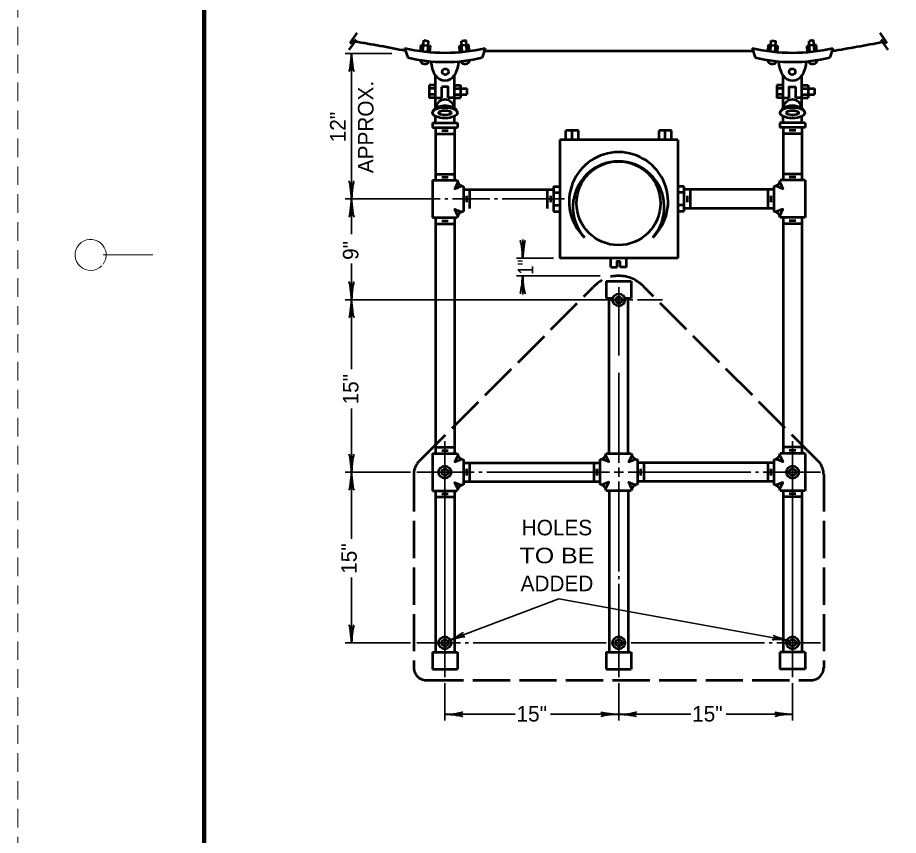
# Model space of a CAD drawing. Extents: x -1 to 679, y 1 to 441.
# Drawn here: x -1.2 to 140.6, y 193.5 to 325.3 of the extents above; entities that cross this region are included whole.
import ezdxf
from ezdxf.enums import TextEntityAlignment as Align

# ---------------------------------------------------------------- set-up
doc = ezdxf.new("R2010")
doc.units = 0
doc.linetypes.add('LONG_DASHED', pattern=[7.5, 6, -1.5])
doc.linetypes.add('MEDIUM_DASHED', pattern=[4.5, 3, -1.5])
doc.layers.add('1', color=7, linetype='Continuous', lineweight=35)
doc.layers.add('61', color=7, linetype='Continuous', lineweight=35)

msp = doc.modelspace()

# ---------------------------------------------------------------- linework, layer by layer
at = {"layer": '1', "linetype": 'MEDIUM_DASHED', "lineweight": 13}
msp.add_line((-1.178, 440.796), (-1.238, 0.756), dxfattribs=at)
at = {"layer": '1', "lineweight": 53}
for p, q in [((52.31, 321.145), (53.457, 322.783)), ((138.783, 321.145), (137.636, 322.783)), ((52.158, 320.046), (53.305, 321.684)), ((52.31, 321.145), (53.305, 321.684)), ((63.653, 319.875), (63.743, 320.896)), ((63.743, 320.896), (65.229, 320.695)), ((64.029, 319.867), (64.181, 321.61)), ((64.181, 321.61), (64.907, 321.469)), ((64.785, 319.723), (64.907, 321.469)), ((65.16, 319.707), (65.229, 320.695)), ((71.413, 320.86), (69.912, 320.692)), ((69.981, 319.708), (69.912, 320.692)), ((70.987, 321.582), (70.234, 321.467)), ((70.356, 319.721), (70.234, 321.467)), ((71.109, 319.836), (70.987, 321.582)), ((71.482, 319.875), (71.413, 320.86)), ((119.611, 319.875), (119.68, 320.86)), ((119.68, 320.86), (121.181, 320.692)), ((119.985, 319.836), (120.107, 321.582)), ((120.107, 321.582), (120.859, 321.467)), ((120.737, 319.721), (120.859, 321.467)), ((121.112, 319.708), (121.181, 320.692)), ((127.351, 320.896), (125.864, 320.695)), ((125.933, 319.707), (125.864, 320.695)), ((126.912, 321.61), (126.186, 321.469)), ((126.308, 319.723), (126.186, 321.469)), ((127.064, 319.867), (126.912, 321.61)), ((127.44, 319.875), (127.351, 320.896)), ((138.936, 320.046), (137.788, 321.684)), ((138.783, 321.145), (137.788, 321.684)), ((61.069, 320.356), (61.569, 318.856)), ((74.069, 320.356), (73.569, 318.856)), ((73.911, 319.881), (117.182, 319.881)), ((117.024, 320.356), (117.524, 318.856)), ((130.024, 320.356), (129.524, 318.856)), ((66.047, 310.652), (66.047, 315.963)), ((69.092, 310.652), (69.092, 315.963)), ((122.001, 310.652), (122.001, 315.963)), ((125.047, 310.652), (125.047, 315.963)), ((66.047, 314.356), (65.047, 314.356)), ((65.047, 314.356), (65.047, 312.356)), ((66.047, 313.856), (65.047, 313.856)), ((67.047, 312.356), (67.047, 314.106)), ((69.092, 314.356), (70.092, 314.356)), ((69.092, 313.856), (71.092, 313.856)), ((70.092, 314.356), (70.092, 312.356)), ((71.092, 313.856), (71.092, 312.856)), ((122.001, 314.356), (121.001, 314.356)), ((121.001, 314.356), (121.001, 312.356)), ((122.001, 313.856), (121.001, 313.856)), ((124.047, 312.356), (124.047, 314.106)), ((125.047, 314.356), (126.047, 314.356)), ((125.047, 313.856), (127.047, 313.856)), ((126.047, 314.356), (126.047, 312.356)), ((127.047, 313.856), (127.047, 312.856)), ((66.047, 312.856), (65.047, 312.856)), ((66.047, 312.356), (65.047, 312.356)), ((66.047, 312.356), (67.047, 312.356)), ((69.092, 312.356), (68.092, 312.356)), ((69.092, 312.856), (71.092, 312.856)), ((69.092, 312.356), (70.092, 312.356)), ((122.001, 312.856), (121.001, 312.856)), ((122.001, 312.356), (121.001, 312.356)), ((122.001, 312.356), (123.001, 312.356)), ((125.047, 312.356), (124.047, 312.356)), ((125.047, 312.856), (127.047, 312.856)), ((125.047, 312.356), (126.047, 312.356)), ((66.047, 308.298), (66.047, 309.356)), ((69.092, 308.298), (69.092, 309.356)), ((122.001, 308.298), (122.001, 309.356)), ((125.047, 308.298), (125.047, 309.356)), ((65.547, 308.298), (69.592, 308.298)), ((65.547, 308.298), (65.547, 307.548)), ((69.592, 308.298), (69.592, 307.548)), ((125.547, 308.298), (121.501, 308.298)), ((121.501, 308.298), (121.501, 307.548)), ((125.547, 308.298), (125.547, 307.548)), ((65.547, 307.548), (69.592, 307.548)), ((66.047, 307.548), (66.047, 299.048)), ((66.047, 306.548), (69.092, 306.548)), ((67.047, 307.048), (68.092, 307.048)), ((69.092, 307.548), (69.092, 299.048)), ((87.047, 305.57), (87.047, 307.07)), ((89.047, 307.07), (87.047, 307.07)), ((88.047, 305.57), (88.047, 307.07)), ((89.047, 305.57), (89.047, 307.07)), ((102.047, 305.57), (102.047, 307.07)), ((104.047, 307.07), (102.047, 307.07)), ((103.047, 305.57), (103.047, 307.07)), ((104.047, 305.57), (104.047, 307.07)), ((125.547, 307.548), (121.501, 307.548)), ((122.001, 307.548), (122.001, 299.048)), ((125.047, 306.548), (122.001, 306.548)), ((124.047, 307.048), (123.001, 307.048)), ((125.047, 307.548), (125.047, 299.048)), ((105.047, 305.57), (86.047, 305.57)), ((86.047, 305.57), (86.047, 286.536)), ((105.047, 305.57), (105.047, 286.536)), ((66.047, 300.048), (69.092, 300.048)), ((67.047, 299.548), (68.092, 299.548)), ((125.047, 300.048), (122.001, 300.048)), ((124.047, 299.548), (123.001, 299.548)), ((65.547, 299.048), (69.546, 299.048)), ((65.547, 299.048), (65.547, 293.048)), ((70.547, 298.07), (70.547, 294.025)), ((85.047, 298.07), (85.047, 294.036)), ((85.047, 298.07), (86.047, 298.07)), ((106.047, 298.07), (105.047, 298.07)), ((106.047, 298.07), (106.047, 294.036)), ((120.547, 298.07), (120.547, 294.025)), ((125.547, 299.048), (121.548, 299.048)), ((125.547, 299.048), (125.547, 293.048)), ((70.547, 297.57), (85.047, 297.57)), ((71.047, 296.57), (71.047, 295.525)), ((71.547, 297.57), (71.547, 294.525)), ((84.047, 297.57), (84.047, 294.525)), ((84.547, 296.57), (84.547, 295.525)), ((85.047, 297.07), (86.047, 297.07)), ((106.047, 297.07), (105.047, 297.07)), ((120.547, 297.57), (106.047, 297.57)), ((106.547, 296.57), (106.547, 295.525)), ((107.047, 297.57), (107.047, 294.525)), ((119.547, 297.57), (119.547, 294.525)), ((120.047, 296.57), (120.047, 295.525)), ((85.047, 295.036), (86.047, 295.036)), ((106.047, 295.036), (105.047, 295.036)), ((85.047, 294.036), (86.047, 294.036)), ((106.047, 294.036), (105.047, 294.036)), ((120.547, 294.525), (106.047, 294.525)), ((65.547, 293.048), (69.542, 293.048)), ((66.047, 293.048), (66.047, 255.048)), ((66.047, 293.048), (69.092, 293.048)), ((67.047, 292.548), (68.092, 292.548)), ((69.092, 293.048), (69.092, 255.048)), ((125.547, 293.048), (121.551, 293.048)), ((122.001, 293.048), (122.001, 255.048)), ((125.047, 293.048), (122.001, 293.048)), ((124.047, 292.548), (123.001, 292.548)), ((125.047, 293.048), (125.047, 255.048)), ((66.047, 292.048), (69.092, 292.048)), ((125.047, 292.048), (122.001, 292.048)), ((105.047, 286.536), (86.047, 286.536)), ((94.297, 285.036), (94.297, 286.536)), ((96.797, 285.036), (96.797, 286.536)), ((95.797, 285.036), (95.797, 286.036)), ((94.297, 285.036), (95.297, 285.036)), ((96.797, 285.036), (95.797, 285.036)), ((93.524, 282.814), (97.569, 282.814)), ((93.524, 282.814), (93.524, 280.064)), ((97.569, 282.814), (97.569, 280.064)), ((93.524, 280.064), (94.595, 280.064)), ((94.024, 255.064), (94.024, 280.064)), ((96.518, 280.064), (97.569, 280.064)), ((97.069, 255.064), (97.069, 280.064)), ((66.047, 256.048), (69.092, 256.048)), ((67.047, 255.548), (68.092, 255.548)), ((125.047, 256.048), (122.001, 256.048)), ((124.047, 255.548), (123.001, 255.548)), ((65.547, 255.048), (69.546, 255.048)), ((65.547, 255.048), (65.547, 249.048)), ((70.547, 254.07), (70.547, 250.025)), ((92.524, 254.07), (92.524, 250.064)), ((93.524, 255.064), (97.569, 255.064)), ((98.572, 254.07), (98.572, 250.058)), ((120.547, 254.07), (120.547, 250.025)), ((125.547, 255.048), (121.548, 255.048)), ((125.547, 255.048), (125.547, 249.048)), ((70.547, 253.57), (92.524, 253.57)), ((71.047, 252.57), (71.047, 251.525)), ((71.547, 253.57), (71.547, 250.525)), ((91.524, 253.57), (91.524, 250.525)), ((92.024, 252.57), (92.024, 251.525)), ((120.547, 253.57), (98.572, 253.57)), ((99.072, 252.57), (99.072, 251.525)), ((99.572, 253.57), (99.572, 250.525)), ((119.547, 253.57), (119.547, 250.525)), ((120.047, 252.57), (120.047, 251.525)), ((70.547, 250.525), (92.524, 250.525)), ((120.547, 250.525), (98.572, 250.525)), ((65.547, 249.048), (69.542, 249.048)), ((66.047, 249.048), (66.047, 223.048)), ((67.047, 248.548), (68.092, 248.548)), ((69.092, 249.048), (69.092, 223.048)), ((93.531, 249.064), (97.565, 249.064)), ((94.031, 249.064), (94.031, 223.064)), ((97.065, 249.064), (97.065, 223.064)), ((125.547, 249.048), (121.551, 249.048)), ((122.001, 249.048), (122.001, 223.048)), ((124.047, 248.548), (123.001, 248.548)), ((125.047, 249.048), (125.047, 223.048)), ((66.047, 248.048), (69.092, 248.048)), ((125.047, 248.048), (122.001, 248.048)), ((65.547, 223.048), (69.592, 223.048)), ((65.547, 223.048), (65.547, 220.298)), ((69.592, 223.048), (69.592, 220.298)), ((93.531, 223.064), (97.576, 223.064)), ((93.531, 223.064), (93.531, 220.314)), ((97.576, 223.064), (97.576, 220.314)), ((125.547, 223.048), (121.501, 223.048)), ((121.501, 223.048), (121.501, 220.298)), ((125.547, 223.048), (125.547, 220.298)), ((65.547, 220.298), (69.592, 220.298)), ((93.531, 220.314), (97.576, 220.314)), ((125.547, 220.298), (121.501, 220.298))]:
    msp.add_line(p, q, dxfattribs=at)
at = {"layer": '1'}
for p, q in [((58.999, 319.477), (51.524, 319.477)), ((52.524, 296.048), (52.524, 319.477)), ((66.797, 296.048), (51.524, 296.048)), ((52.524, 296.048), (52.524, 290.352)), ((67.547, 296.048), (68.047, 296.048)), ((68.797, 296.048), (74.797, 296.048)), ((75.547, 296.048), (76.047, 296.048)), ((76.797, 296.048), (86.797, 296.048)), ((80.092, 286.492), (80.092, 289.492)), ((79.092, 286.492), (85.047, 286.492)), ((79.092, 283.672), (92.569, 283.672)), ((80.092, 283.672), (80.092, 280.672)), ((95.547, 281.814), (95.547, 270.814)), ((51.524, 279.814), (96.569, 279.814)), ((97.319, 279.814), (97.819, 279.814)), ((98.569, 279.814), (102.569, 279.814)), ((95.547, 268.064), (95.547, 253.548)), ((67.546, 257.048), (67.546, 219.048)), ((123.547, 257.048), (123.547, 219.048)), ((62.047, 252.048), (51.524, 252.048)), ((63.047, 252.048), (72.297, 252.048)), ((73.047, 252.048), (73.547, 252.048)), ((74.297, 252.048), (94.047, 252.048)), ((94.797, 252.048), (96.297, 252.048)), ((116.797, 252.048), (97.047, 252.048)), ((118.047, 252.048), (117.547, 252.048)), ((128.047, 252.048), (118.797, 252.048)), ((95.547, 250.548), (95.547, 236.064)), ((52.524, 235.103), (52.524, 224.548)), ((95.547, 235.314), (95.547, 234.814)), ((95.547, 234.064), (95.547, 219.048)), ((62.047, 224.548), (51.524, 224.548)), ((63.047, 224.548), (70.092, 224.548)), ((70.842, 224.548), (71.342, 224.548)), ((72.092, 224.548), (93.531, 224.548)), ((94.548, 224.548), (96.548, 224.548)), ((119.001, 224.548), (97.565, 224.548)), ((120.251, 224.548), (119.751, 224.548)), ((128.047, 224.548), (121.001, 224.548)), ((67.546, 218.048), (67.546, 212.048)), ((95.547, 218.048), (95.547, 212.048)), ((123.547, 218.048), (123.547, 212.048)), ((67.546, 213.048), (78.873, 213.048)), ((112.832, 213.048), (123.547, 213.048))]:
    msp.add_line(p, q, dxfattribs=at)
at = {"layer": '1', "linetype": 'LONG_DASHED', "lineweight": 53}
for p, q in [((63.425, 253.819), (91.426, 281.82)), ((127.668, 253.819), (99.667, 281.82)), ((62.547, 251.698), (62.547, 220.548)), ((128.547, 251.698), (128.547, 220.548)), ((64.547, 218.548), (126.547, 218.548))]:
    msp.add_line(p, q, dxfattribs=at)
at = {"layer": '1', "lineweight": 53}
for points in [[(68.092, 312.356), (68.092, 314.106), (67.047, 314.106)], [(123.001, 312.356), (123.001, 314.106), (124.047, 314.106)], [(69.624, 298.745), (69.139, 297.698), (70.23, 298.146)], [(121.469, 298.745), (121.954, 297.698), (120.863, 298.146)], [(69.62, 293.35), (69.135, 294.397), (70.227, 293.949)], [(121.473, 293.35), (121.958, 294.397), (120.867, 293.949)], [(95.297, 285.036), (95.297, 286.036), (95.797, 286.036)], [(69.624, 254.745), (69.139, 253.698), (70.23, 254.146)], [(93.444, 254.745), (93.929, 253.698), (92.838, 254.146)], [(97.649, 254.745), (97.164, 253.698), (98.255, 254.146)], [(121.469, 254.745), (121.954, 253.698), (120.863, 254.146)], [(69.62, 249.35), (69.135, 250.397), (70.227, 249.949)], [(93.451, 249.389), (93.936, 250.436), (92.844, 249.988)], [(97.645, 249.383), (97.16, 250.43), (98.252, 249.982)], [(121.473, 249.35), (121.958, 250.397), (120.867, 249.949)]]:
    msp.add_lwpolyline(points, dxfattribs=at)
at = {"layer": '1'}
for points in [[(52.524, 285.636), (52.524, 279.814), (52.524, 268.656)], [(52.524, 262.323), (52.524, 252.048), (52.524, 241.301)], [(95.547, 251.298), (95.547, 252.048), (95.547, 252.798)], [(67.962, 224.861), (85.913, 231.618), (123.154, 224.888)], [(84.552, 213.048), (95.547, 213.048), (107.153, 213.048)]]:
    msp.add_lwpolyline(points, dxfattribs=at)
at = {"layer": '1', "lineweight": 53}
for centre, radius in [((67.614, 316.528), 0.5), ((123.479, 316.528), 0.5), ((95.515, 295.35), 6.75), ((95.556, 279.789), 1), ((95.571, 279.789), 0.5), ((67.551, 252.042), 1), ((67.565, 252.042), 0.5), ((123.542, 252.042), 1), ((123.528, 252.042), 0.5), ((67.552, 224.555), 1), ((95.548, 224.555), 1), ((123.541, 224.555), 1), ((67.566, 224.555), 0.5), ((95.562, 224.555), 0.5), ((123.527, 224.555), 0.5)]:
    msp.add_circle(centre, radius, dxfattribs=at)
for centre, radius, start, end in [((30.33, 172.228), 150.851, 78.18089, 81.33006), ((87.663, 576.7), 260.264, 279.33196, 281.15709), ((67.569, 348.147), 28.542, 256.83593, 283.1638), ((123.524, 348.147), 28.542, 256.8362, 283.16407), ((67.569, 342.481), 24.375, 255.74997, 284.25003), ((64.33, 318.618), 0.821, 192.33045, 332.21364), ((70.81, 318.618), 0.821, 207.78636, 347.66955), ((123.524, 342.481), 24.375, 255.74997, 284.25003), ((120.283, 318.618), 0.821, 192.33045, 332.21364), ((126.763, 318.618), 0.821, 207.78636, 347.66955), ((67.569, 310.52), 1.528, 4.98578, 175.01422), ((123.524, 310.52), 1.528, 4.98578, 175.01422), ((95.526, 295.614), 7.975, 313.60282, 226.39718), ((95.526, 294.736), 7.364, 318.31863, 221.68137), ((70.642, 299.169), 1.103, 186.32364, 248.08344), ((70.642, 299.169), 1.103, 202.62687, 248.08262), ((70.642, 299.169), 1.103, 248.08344, 265.0377), ((120.451, 299.169), 1.103, 274.9623, 291.91656), ((120.451, 299.169), 1.103, 291.91656, 353.67636), ((120.451, 299.169), 1.103, 291.91738, 337.37313), ((70.638, 292.926), 1.103, 111.91656, 173.65459), ((70.638, 292.926), 1.103, 111.91738, 157.37313), ((70.638, 292.926), 1.103, 94.77118, 111.91656), ((120.455, 292.926), 1.103, 68.08344, 85.22882), ((120.455, 292.926), 1.103, 6.34541, 68.08344), ((120.455, 292.926), 1.103, 22.62687, 68.08262), ((70.642, 255.169), 1.103, 186.32364, 248.08344), ((70.642, 255.169), 1.103, 202.62687, 248.08262), ((70.642, 255.169), 1.103, 248.08344, 265.0377), ((92.426, 255.169), 1.103, 275.11437, 291.91656), ((92.426, 255.169), 1.103, 291.91656, 354.5292), ((92.426, 255.169), 1.103, 291.91738, 337.37313), ((98.667, 255.169), 1.103, 185.4708, 248.08344), ((98.667, 255.169), 1.103, 202.62687, 248.08262), ((98.667, 255.169), 1.103, 248.08344, 265.0377), ((120.451, 255.169), 1.103, 274.9623, 291.91656), ((120.451, 255.169), 1.103, 291.91656, 353.67636), ((120.451, 255.169), 1.103, 291.91738, 337.37313), ((70.638, 248.926), 1.103, 111.91656, 173.65459), ((70.638, 248.926), 1.103, 111.91738, 157.37313), ((70.638, 248.926), 1.103, 94.77118, 111.91656), ((92.432, 248.965), 1.103, 68.08344, 85.22882), ((92.432, 248.965), 1.103, 5.16652, 68.08344), ((92.432, 248.965), 1.103, 22.62687, 68.08262), ((98.664, 248.959), 1.103, 111.91656, 174.5292), ((98.664, 248.959), 1.103, 111.91738, 157.37313), ((98.664, 248.959), 1.103, 94.77118, 111.91656), ((120.455, 248.926), 1.103, 68.08344, 85.22882), ((120.455, 248.926), 1.103, 6.34541, 68.08344), ((120.455, 248.926), 1.103, 22.62687, 68.08262)]:
    msp.add_arc(centre, radius, start, end, dxfattribs=at)
at = {"layer": '1', "linetype": 'LONG_DASHED', "lineweight": 53}
for centre, radius, start, end in [((95.547, 278.15), 5.518, 41.68937, 138.31063), ((65.547, 251.698), 3, 135, 180), ((125.547, 251.698), 3, 0, 45), ((64.547, 220.548), 2, 180, 270), ((126.547, 220.548), 2, 270, 0)]:
    msp.add_arc(centre, radius, start, end, dxfattribs=at)
at = {"layer": '1', "lineweight": 40}
for centre, major_axis, ratio, start_param, end_param in [((52.312, 318.357), (0.176, 1.756), 0.07063, 3.1407148, 5.41811), ((52.312, 318.357), (0.176, 1.756), 0.07063, 3.1407148, 5.41811), ((52.8, 318.386), (-0.156, 1.786), 0.122415, 0.8963533, 3.1415927), ((52.8, 318.386), (-0.156, 1.786), 0.122415, 0.8963533, 3.1415927), ((52.248, 297.139), (0.156, -1.786), 0.122415, 0.8963533, 3.1415927), ((52.248, 297.139), (0.156, -1.786), 0.122415, 0.8963533, 3.1415927), ((52.736, 297.168), (-0.176, -1.756), 0.07063, 3.1407148, 5.41811), ((52.736, 297.168), (-0.176, -1.756), 0.07063, 3.1407148, 5.41811), ((52.312, 294.927), (0.176, 1.756), 0.07063, 3.1407148, 5.41811), ((52.312, 294.927), (0.176, 1.756), 0.07063, 3.1407148, 5.41811), ((52.8, 294.957), (-0.156, 1.786), 0.122415, 0.8963533, 3.1415927), ((52.8, 294.957), (-0.156, 1.786), 0.122415, 0.8963533, 3.1415927), ((79.815, 287.583), (0.156, -1.786), 0.122415, 0.8963533, 3.1415927), ((79.815, 287.583), (0.156, -1.786), 0.122415, 0.8963533, 3.1415927), ((80.303, 287.613), (-0.176, -1.756), 0.07063, 3.1407148, 5.41811), ((80.303, 287.613), (-0.176, -1.756), 0.07063, 3.1407148, 5.41811), ((79.88, 282.552), (0.176, 1.756), 0.07063, 3.1407148, 5.41811), ((80.368, 282.581), (-0.156, 1.786), 0.122415, 0.8963533, 3.1415927), ((52.248, 280.905), (0.156, -1.786), 0.122415, 0.8963533, 3.1415927), ((52.248, 280.905), (0.156, -1.786), 0.122415, 0.8963533, 3.1415927), ((52.736, 280.935), (-0.176, -1.756), 0.07063, 3.1407148, 5.41811), ((52.736, 280.935), (-0.176, -1.756), 0.07063, 3.1407148, 5.41811), ((52.312, 278.693), (0.176, 1.756), 0.07063, 3.1407148, 5.41811), ((52.312, 278.693), (0.176, 1.756), 0.07063, 3.1407148, 5.41811), ((52.8, 278.723), (-0.156, 1.786), 0.122415, 0.8963533, 3.1415927), ((52.8, 278.723), (-0.156, 1.786), 0.122415, 0.8963533, 3.1415927), ((52.248, 253.139), (0.156, -1.786), 0.122415, 0.8963533, 3.1415927), ((52.248, 253.139), (0.156, -1.786), 0.122415, 0.8963533, 3.1415927), ((52.736, 253.168), (-0.176, -1.756), 0.07063, 3.1407148, 5.41811), ((52.736, 253.168), (-0.176, -1.756), 0.07063, 3.1407148, 5.41811), ((52.312, 250.927), (0.176, 1.756), 0.07063, 3.1407148, 5.41811), ((52.312, 250.927), (0.176, 1.756), 0.07063, 3.1407148, 5.41811), ((52.8, 250.957), (-0.156, 1.786), 0.122415, 0.8963533, 3.1415927), ((52.8, 250.957), (-0.156, 1.786), 0.122415, 0.8963533, 3.1415927), ((52.248, 225.639), (0.156, -1.786), 0.122415, 0.8963533, 3.1415927), ((52.736, 225.668), (-0.176, -1.756), 0.07063, 3.1407148, 5.41811), ((68.886, 225.504), (-1.616, -0.775), 0.122415, 0.8963533, 3.1415927), ((68.886, 225.504), (-1.616, -0.775), 0.122415, 0.8963533, 3.1415927), ((69.085, 225.058), (1.706, 0.454), 0.07063, 6.2823074, 8.5597026), ((69.085, 225.058), (1.706, 0.454), 0.07063, 6.2823074, 8.5597026), ((122.089, 225.296), (1.697, -0.485), 0.07063, 3.1407148, 5.41811), ((122.089, 225.296), (1.697, -0.485), 0.07063, 3.1407148, 5.41811), ((122.031, 224.81), (1.785, -0.164), 0.122415, 0.8963533, 3.1415927), ((122.031, 224.81), (1.785, -0.164), 0.122415, 0.8963533, 3.1415927), ((68.637, 213.324), (-1.786, -0.156), 0.122415, 0.8963533, 3.1415927), ((68.637, 213.324), (-1.786, -0.156), 0.122415, 0.8963533, 3.1415927), ((68.667, 212.836), (-1.756, 0.176), 0.07063, 3.1407148, 5.41811), ((68.667, 212.836), (-1.756, 0.176), 0.07063, 3.1407148, 5.41811), ((94.455, 212.772), (1.786, 0.156), 0.122415, 0.8963533, 3.1415927), ((94.455, 212.772), (1.786, 0.156), 0.122415, 0.8963533, 3.1415927), ((94.426, 213.26), (1.756, -0.176), 0.07063, 3.1407148, 5.41811), ((94.426, 213.26), (1.756, -0.176), 0.07063, 3.1407148, 5.41811), ((96.667, 212.836), (-1.756, 0.176), 0.07063, 3.1407148, 5.41811), ((96.667, 212.836), (-1.756, 0.176), 0.07063, 3.1407148, 5.41811), ((96.638, 213.324), (-1.786, -0.156), 0.122415, 0.8963533, 3.1415927), ((96.638, 213.324), (-1.786, -0.156), 0.122415, 0.8963533, 3.1415927), ((122.456, 212.772), (1.786, 0.156), 0.122415, 0.8963533, 3.1415927), ((122.456, 212.772), (1.786, 0.156), 0.122415, 0.8963533, 3.1415927), ((122.427, 213.26), (1.756, -0.176), 0.07063, 3.1407148, 5.41811), ((122.427, 213.26), (1.756, -0.176), 0.07063, 3.1407148, 5.41811)]:
    msp.add_ellipse(centre, major_axis=major_axis, ratio=ratio, start_param=start_param, end_param=end_param, dxfattribs=at)
at = {"layer": '1', "lineweight": 53}
for centre, major_axis, ratio, start_param, end_param in [((67.569, 318.356), (0, 3.25), 0.692308, 1.615522, 4.6676498), ((123.524, 318.356), (0, 3.25), 0.692308, 1.6155355, 4.6676633), ((67.569, 309.923), (2, 0), 0.5625, 6.2831853, 9.424778), ((123.524, 309.923), (-2, 0), 0.5625, 3.1415927, 6.2831853)]:
    msp.add_ellipse(centre, major_axis=major_axis, ratio=ratio, start_param=start_param, end_param=end_param, dxfattribs=at)
for centre, major_axis, ratio in [((67.569, 309.923), (2, 0), 0.4375), ((123.524, 309.923), (-2, 0), 0.4375), ((67.569, 309.923), (1, 0), 0.375), ((123.524, 309.923), (-1, 0), 0.375)]:
    msp.add_ellipse(centre, major_axis=major_axis, ratio=ratio, dxfattribs=at)
at = {"layer": '61', "lineweight": 13}
msp.add_line((12.522, 287.036), (20.522, 287.036), dxfattribs=at)
at = {"layer": '61', "lineweight": 158}
msp.add_lwpolyline([(667.862, 430.796), (28.822, 430.796), (28.822, 10.776)], dxfattribs=at)
at = {"layer": '61', "lineweight": 13}
msp.add_arc((10.52, 287.037), 2.5, 323.13009, 315.37577, dxfattribs=at)

# ---------------------------------------------------------------- texts
at = {"layer": '1'}
for s, p in [('APPROX.', (56.062, 307.632)), ('12"', (51.562, 307.632))]:
    msp.add_text(s, height=2.5, rotation=90, dxfattribs=at).set_placement(p, align=Align.CENTER)
for s, p in [('9"', (53.631, 286.231)), ('15"', (53.631, 262.958)), ('15"', (53.364, 235.671))]:
    msp.add_text(s, height=2.5, rotation=90, dxfattribs=at).set_placement(p)
at = {"layer": '1', "width": 0.8}
msp.add_text('1"', height=2.5, rotation=90, dxfattribs=at).set_placement((81.785, 283.839))
at = {"layer": '1'}
for s, p in [('HOLES', (85.605, 241.87)), ('ADDED', (85.605, 232.87))]:
    msp.add_text(s, height=2.5, dxfattribs=at).set_placement(p, align=Align.CENTER)
at = {"layer": '1', "width": 1.2}
msp.add_text('TO BE', height=2.5, dxfattribs=at).set_placement((85.605, 237.37), align=Align.CENTER)
at = {"layer": '1'}
for p in [(79.094, 211.88), (107.367, 211.88)]:
    msp.add_text('15"', height=2.5, dxfattribs=at).set_placement(p)

doc.saveas('drawing.dxf')
